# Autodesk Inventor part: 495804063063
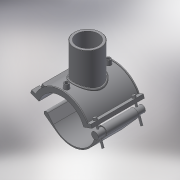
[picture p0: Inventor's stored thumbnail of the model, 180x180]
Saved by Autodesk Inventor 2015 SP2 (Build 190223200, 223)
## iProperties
Created: 2017-07
Part Number: 495804063063
Material: Generic
Description: PLASSON BRANCH SADDLE 63-63
Document SubType Name: Modeling
Designer: KIM
Density: 1 g/cm^3
Appearance: Default
Author: KIM
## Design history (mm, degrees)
derived "495804.ipt"
feature "Solid1::495804.ipt"
feature "Solid2::495804.ipt"
tag "TaggingFeature1"
body "Solid1"
body "Solid2"
other parameters: "d0" = 63, "d3" = 15.75, "d4" = 118, "d5" = 0, "d6" = 0.1, "d8" = 0, "d19" = 6, "d20" = 6, "d21" = 70.8, "d23" = 0, "d24" = 35.4, "d26" = 0, "d27" = 3, "d28" = 3, "d29" = 3, "d30" = 21, "d31" = 6, "d32" = 0, "d33" = 0, "d34" = 0.6, "d40" = 42.12, "d41" = 69.3, "d43" = 0, "d45" = 0, "d47" = 134.5, "d48" = 63, "d50" = 0, "d70" = 15, "d72" = 0, "d73" = 6, "d75" = 5, "d76" = 0, "d77" = 3.15, "d78" = 61.5, "d79" = 15, "d80" = 47.2, "d82" = 5 deg, "d84" = 4, "d85" = 14, "d86" = 0, "d87" = 3, "d88" = 0, "d89" = 1, "d90" = 1, "d91" = 94.4, "d92" = 0, "d93" = 0.5, "d94" = 33.15789, "d96" = 82.62, "d97" = 2.36, "d98" = 0, "d102" = 1.89, "d103" = 50.4, "d105" = 0, "d109" = -31.33333, "d117" = 0.63, "d120" = 140 deg, "d121" = 24.228, "d122" = 20 deg, "d123" = 162, "d124" = 48.6, "d126" = 0, "d143" = 66.15, "d150" = 11.34, "d159" = 3.6, "d161" = 1.575, "d162" = 70.8, "d163" = 0, "d167" = 12.6, "d168" = 36.81818, "d173" = 1, "d175" = 31.5, "d176" = 20 deg, "d177" = 4.41, "d178" = 18, "d180" = 0, "d185" = 38.35, "d186" = 38.35, "d187" = 40.5, "d188" = 5.4, "d189" = 4.41, "d190" = 0, "d191" = 60.75, "d200" = 9, "d202" = 0, "d216" = 106.2, "d217" = 0, "d221" = 43.66, "d222" = 4.41, "d223" = 2.646, "d224" = 31.5, "d225" = 2.646, "d227" = 9.072, "d230" = 39.06, "d236" = 20 deg, "d237" = 47.5, "d238" = 20 deg, "d239" = 4.41, "d_" = 63, "H_" = 94, "L_" = 118, "d_t" = 6, "d_1" = 63, "H_1" = 85, "d1" = 81, "d148" = 1.575, "d160" = 1.575
